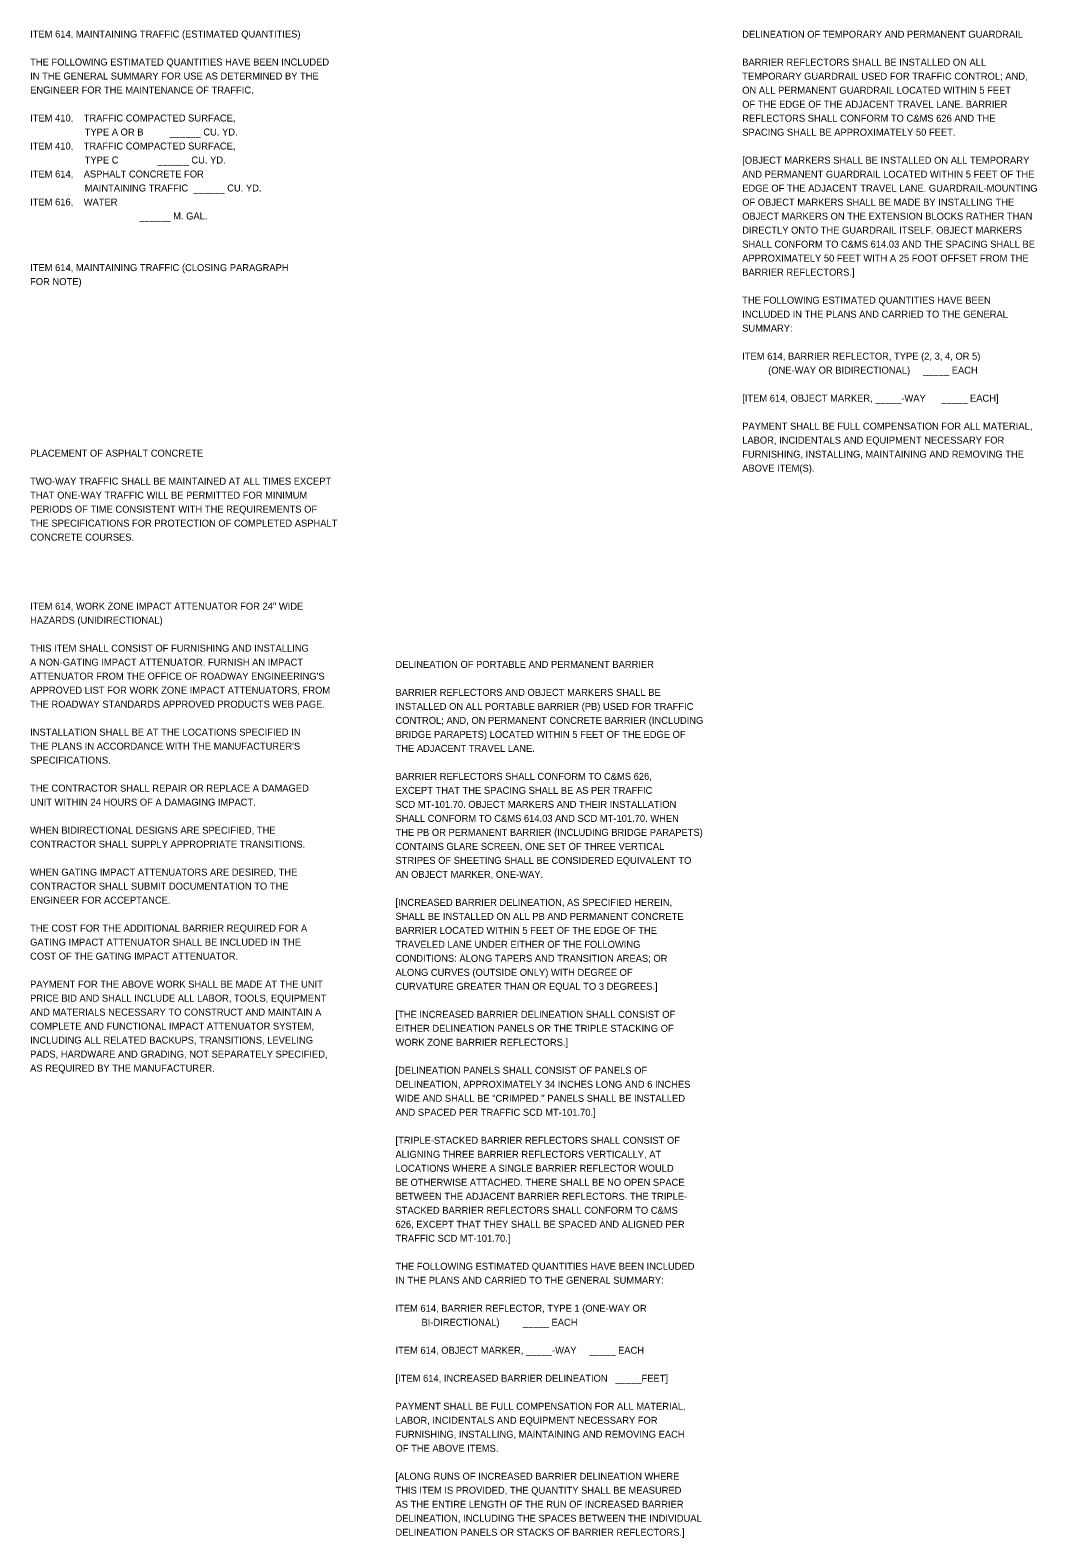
# Model space of a CAD drawing. Extents: x -59 to 65, y -12 to 46.
# Drawn here: x 45.07 to 65.21, y -12.01 to 18.15 of the extents above; entities that cross this region are included whole.
import ezdxf

# ---------------------------------------------------------------- set-up
doc = ezdxf.new("R2010")
doc.units = 0
doc.layers.add('SH_Text', color=7, linetype='Continuous')

msp = doc.modelspace()

# ---------------------------------------------------------------- texts
at = {"layer": 'SH_Text'}
for s, p in [('ITEM 614, MAINTAINING TRAFFIC (ESTIMATED QUANTITIES)', (45.071, 18.005)), ('DELINEATION OF TEMPORARY AND PERMANENT GUARDRAIL', (59.316, 18.001)), ('THE FOLLOWING ESTIMATED QUANTITIES HAVE BEEN INCLUDED', (45.071, 17.445)), ('BARRIER REFLECTORS SHALL BE INSTALLED ON ALL', (59.316, 17.441)), ('IN THE GENERAL SUMMARY FOR USE AS DETERMINED BY THE', (45.071, 17.165)), ('TEMPORARY GUARDRAIL USED FOR TRAFFIC CONTROL; AND,', (59.316, 17.161)), ('ENGINEER FOR THE MAINTENANCE OF TRAFFIC.', (45.071, 16.885)), ('ON ALL PERMANENT GUARDRAIL LOCATED WITHIN 5 FEET', (59.316, 16.881)), ('OF THE EDGE OF THE ADJACENT TRAVEL LANE. BARRIER', (59.316, 16.601)), ('ITEM 410,    TRAFFIC COMPACTED SURFACE,', (45.071, 16.325)), ('REFLECTORS SHALL CONFORM TO C&MS 626 AND THE', (59.316, 16.321)), ('                     TYPE A OR B          ______ CU. YD.', (45.071, 16.045)), ('SPACING SHALL BE APPROXIMATELY 50 FEET.', (59.316, 16.041)), ('ITEM 410,    TRAFFIC COMPACTED SURFACE,', (45.071, 15.765)), ('                     TYPE C               ______ CU. YD.', (45.071, 15.485)), ('[OBJECT MARKERS SHALL BE INSTALLED ON ALL TEMPORARY', (59.316, 15.481)), ('ITEM 614,    ASPHALT CONCRETE FOR', (45.071, 15.205)), ('AND PERMANENT GUARDRAIL LOCATED WITHIN 5 FEET OF THE', (59.316, 15.201)), ('ITEM 616,    WATER', (45.071, 14.645)), ('                     MAINTAINING TRAFFIC  ______ CU. YD.', (45.071, 14.925)), ('OF OBJECT MARKERS SHALL BE MADE BY INSTALLING THE', (59.316, 14.641)), ('EDGE OF THE ADJACENT TRAVEL LANE. GUARDRAIL-MOUNTING', (59.316, 14.921)), ('                                          ______ M. GAL.', (45.071, 14.365)), ('OBJECT MARKERS ON THE EXTENSION BLOCKS RATHER THAN', (59.316, 14.361)), ('DIRECTLY ONTO THE GUARDRAIL ITSELF. OBJECT MARKERS', (59.316, 14.081)), ('SHALL CONFORM TO C&MS 614.03 AND THE SPACING SHALL BE', (59.316, 13.801)), ('APPROXIMATELY 50 FEET WITH A 25 FOOT OFFSET FROM THE', (59.316, 13.521)), ('ITEM 614, MAINTAINING TRAFFIC (CLOSING PARAGRAPH', (45.071, 13.333)), ('BARRIER REFLECTORS.]', (59.316, 13.241)), ('FOR NOTE)', (45.071, 13.053)), ('THE FOLLOWING ESTIMATED QUANTITIES HAVE BEEN', (59.316, 12.681)), ('INCLUDED IN THE PLANS AND CARRIED TO THE GENERAL', (59.316, 12.401)), ('SUMMARY:', (59.316, 12.121)), ('ITEM 614, BARRIER REFLECTOR, TYPE (2, 3, 4, OR 5)', (59.316, 11.561)), ('          (ONE-WAY OR BIDIRECTIONAL)     _____ EACH', (59.316, 11.281)), ('[ITEM 614, OBJECT MARKER, _____-WAY      _____ EACH]', (59.316, 10.721)), ('PAYMENT SHALL BE FULL COMPENSATION FOR ALL MATERIAL,', (59.316, 10.161)), ('LABOR, INCIDENTALS AND EQUIPMENT NECESSARY FOR', (59.316, 9.881)), ('PLACEMENT OF ASPHALT CONCRETE', (45.071, 9.621)), ('FURNISHING, INSTALLING, MAINTAINING AND REMOVING THE', (59.316, 9.601)), ('ABOVE ITEM(S).', (59.316, 9.321)), ('TWO-WAY TRAFFIC SHALL BE MAINTAINED AT ALL TIMES EXCEPT', (45.071, 9.061)), ('THAT ONE-WAY TRAFFIC WILL BE PERMITTED FOR MINIMUM', (45.071, 8.781)), ('PERIODS OF TIME CONSISTENT WITH THE REQUIREMENTS OF', (45.071, 8.501)), ('THE SPECIFICATIONS FOR PROTECTION OF COMPLETED ASPHALT', (45.071, 8.221)), ('CONCRETE COURSES.', (45.071, 7.941)), ('ITEM 614, WORK ZONE IMPACT ATTENUATOR FOR 24" WIDE', (45.071, 6.56)), ('HAZARDS (UNIDIRECTIONAL)', (45.071, 6.28)), ('THIS ITEM SHALL CONSIST OF FURNISHING AND INSTALLING', (45.071, 5.72)), ('A NON-GATING IMPACT ATTENUATOR. FURNISH AN IMPACT', (45.071, 5.44)), ('DELINEATION OF PORTABLE AND PERMANENT BARRIER', (52.38, 5.396)), ("ATTENUATOR FROM THE OFFICE OF ROADWAY ENGINEERING'S", (45.071, 5.16)), ('APPROVED LIST FOR WORK ZONE IMPACT ATTENUATORS, FROM', (45.071, 4.88)), ('BARRIER REFLECTORS AND OBJECT MARKERS SHALL BE', (52.38, 4.836)), ('THE ROADWAY STANDARDS APPROVED PRODUCTS WEB PAGE.', (45.071, 4.6)), ('INSTALLED ON ALL PORTABLE BARRIER (PB) USED FOR TRAFFIC', (52.38, 4.556)), ('CONTROL; AND, ON PERMANENT CONCRETE BARRIER (INCLUDING', (52.38, 4.276)), ('INSTALLATION SHALL BE AT THE LOCATIONS SPECIFIED IN', (45.071, 4.04)), ('BRIDGE PARAPETS) LOCATED WITHIN 5 FEET OF THE EDGE OF', (52.38, 3.996)), ("THE PLANS IN ACCORDANCE WITH THE MANUFACTURER'S", (45.071, 3.76)), ('SPECIFICATIONS.', (45.071, 3.48)), ('THE ADJACENT TRAVEL LANE.', (52.38, 3.716)), ('THE CONTRACTOR SHALL REPAIR OR REPLACE A DAMAGED', (45.071, 2.92)), ('BARRIER REFLECTORS SHALL CONFORM TO C&MS 626,', (52.38, 3.156)), ('EXCEPT THAT THE SPACING SHALL BE AS PER TRAFFIC', (52.38, 2.876)), ('UNIT WITHIN 24 HOURS OF A DAMAGING IMPACT.', (45.071, 2.64)), ('SCD MT-101.70. OBJECT MARKERS AND THEIR INSTALLATION', (52.38, 2.596)), ('SHALL CONFORM TO C&MS 614.03 AND SCD MT-101.70. WHEN', (52.38, 2.316)), ('WHEN BIDIRECTIONAL DESIGNS ARE SPECIFIED, THE', (45.071, 2.08)), ('THE PB OR PERMANENT BARRIER (INCLUDING BRIDGE PARAPETS)', (52.38, 2.036)), ('CONTRACTOR SHALL SUPPLY APPROPRIATE TRANSITIONS.', (45.071, 1.8)), ('CONTAINS GLARE SCREEN, ONE SET OF THREE VERTICAL', (52.38, 1.756)), ('STRIPES OF SHEETING SHALL BE CONSIDERED EQUIVALENT TO', (52.38, 1.476)), ('WHEN GATING IMPACT ATTENUATORS ARE DESIRED, THE', (45.071, 1.24)), ('AN OBJECT MARKER, ONE-WAY.', (52.38, 1.196)), ('CONTRACTOR SHALL SUBMIT DOCUMENTATION TO THE', (45.071, 0.96)), ('ENGINEER FOR ACCEPTANCE.', (45.071, 0.68)), ('[INCREASED BARRIER DELINEATION, AS SPECIFIED HEREIN,', (52.38, 0.636)), ('SHALL BE INSTALLED ON ALL PB AND PERMANENT CONCRETE', (52.38, 0.356)), ('THE COST FOR THE ADDITIONAL BARRIER REQUIRED FOR A', (45.071, 0.12)), ('BARRIER LOCATED WITHIN 5 FEET OF THE EDGE OF THE', (52.38, 0.076)), ('GATING IMPACT ATTENUATOR SHALL BE INCLUDED IN THE', (45.071, -0.16)), ('COST OF THE GATING IMPACT ATTENUATOR.', (45.071, -0.44)), ('TRAVELED LANE UNDER EITHER OF THE FOLLOWING', (52.38, -0.204)), ('CONDITIONS: ALONG TAPERS AND TRANSITION AREAS; OR', (52.38, -0.484)), ('PAYMENT FOR THE ABOVE WORK SHALL BE MADE AT THE UNIT', (45.071, -1)), ('ALONG CURVES (OUTSIDE ONLY) WITH DEGREE OF', (52.38, -0.764)), ('CURVATURE GREATER THAN OR EQUAL TO 3 DEGREES.]', (52.38, -1.044)), ('PRICE BID AND SHALL INCLUDE ALL LABOR, TOOLS, EQUIPMENT', (45.071, -1.28)), ('AND MATERIALS NECESSARY TO CONSTRUCT AND MAINTAIN A', (45.071, -1.56)), ('[THE INCREASED BARRIER DELINEATION SHALL CONSIST OF', (52.38, -1.604)), ('COMPLETE AND FUNCTIONAL IMPACT ATTENUATOR SYSTEM,', (45.071, -1.84)), ('EITHER DELINEATION PANELS OR THE TRIPLE STACKING OF', (52.38, -1.884)), ('INCLUDING ALL RELATED BACKUPS, TRANSITIONS, LEVELING', (45.071, -2.12)), ('WORK ZONE BARRIER REFLECTORS.]', (52.38, -2.164)), ('PADS, HARDWARE AND GRADING, NOT SEPARATELY SPECIFIED,', (45.071, -2.4)), ('AS REQUIRED BY THE MANUFACTURER.', (45.071, -2.68)), ('[DELINEATION PANELS SHALL CONSIST OF PANELS OF', (52.38, -2.724)), ('DELINEATION, APPROXIMATELY 34 INCHES LONG AND 6 INCHES', (52.38, -3.004)), ('WIDE AND SHALL BE "CRIMPED." PANELS SHALL BE INSTALLED', (52.38, -3.284)), ('AND SPACED PER TRAFFIC SCD MT-101.70.]', (52.38, -3.564)), ('[TRIPLE-STACKED BARRIER REFLECTORS SHALL CONSIST OF', (52.38, -4.124)), ('ALIGNING THREE BARRIER REFLECTORS VERTICALLY, AT', (52.38, -4.404)), ('LOCATIONS WHERE A SINGLE BARRIER REFLECTOR WOULD', (52.38, -4.684)), ('BE OTHERWISE ATTACHED. THERE SHALL BE NO OPEN SPACE', (52.38, -4.964)), ('BETWEEN THE ADJACENT BARRIER REFLECTORS. THE TRIPLE-', (52.38, -5.244)), ('STACKED BARRIER REFLECTORS SHALL CONFORM TO C&MS', (52.38, -5.524)), ('626, EXCEPT THAT THEY SHALL BE SPACED AND ALIGNED PER', (52.38, -5.804)), ('TRAFFIC SCD MT-101.70.]', (52.38, -6.084)), ('THE FOLLOWING ESTIMATED QUANTITIES HAVE BEEN INCLUDED', (52.38, -6.644)), ('IN THE PLANS AND CARRIED TO THE GENERAL SUMMARY:', (52.38, -6.924)), ('ITEM 614, BARRIER REFLECTOR, TYPE 1 (ONE-WAY OR', (52.38, -7.484)), ('          BI-DIRECTIONAL)         _____ EACH', (52.38, -7.764)), ('ITEM 614, OBJECT MARKER, _____-WAY     _____ EACH', (52.38, -8.324)), ('[ITEM 614, INCREASED BARRIER DELINEATION   _____FEET]', (52.38, -8.884)), ('PAYMENT SHALL BE FULL COMPENSATION FOR ALL MATERIAL,', (52.38, -9.444)), ('LABOR, INCIDENTALS AND EQUIPMENT NECESSARY FOR', (52.38, -9.724)), ('FURNISHING, INSTALLING, MAINTAINING AND REMOVING EACH', (52.38, -10.004)), ('OF THE ABOVE ITEMS.', (52.38, -10.284)), ('[ALONG RUNS OF INCREASED BARRIER DELINEATION WHERE', (52.38, -10.844)), ('THIS ITEM IS PROVIDED, THE QUANTITY SHALL BE MEASURED', (52.38, -11.124)), ('AS THE ENTIRE LENGTH OF THE RUN OF INCREASED BARRIER', (52.38, -11.404)), ('DELINEATION, INCLUDING THE SPACES BETWEEN THE INDIVIDUAL', (52.38, -11.684)), ('DELINEATION PANELS OR STACKS OF BARRIER REFLECTORS.]', (52.38, -11.964))]:
    msp.add_text(s, height=0.14, dxfattribs=at).set_placement(p)

doc.saveas('drawing.dxf')
